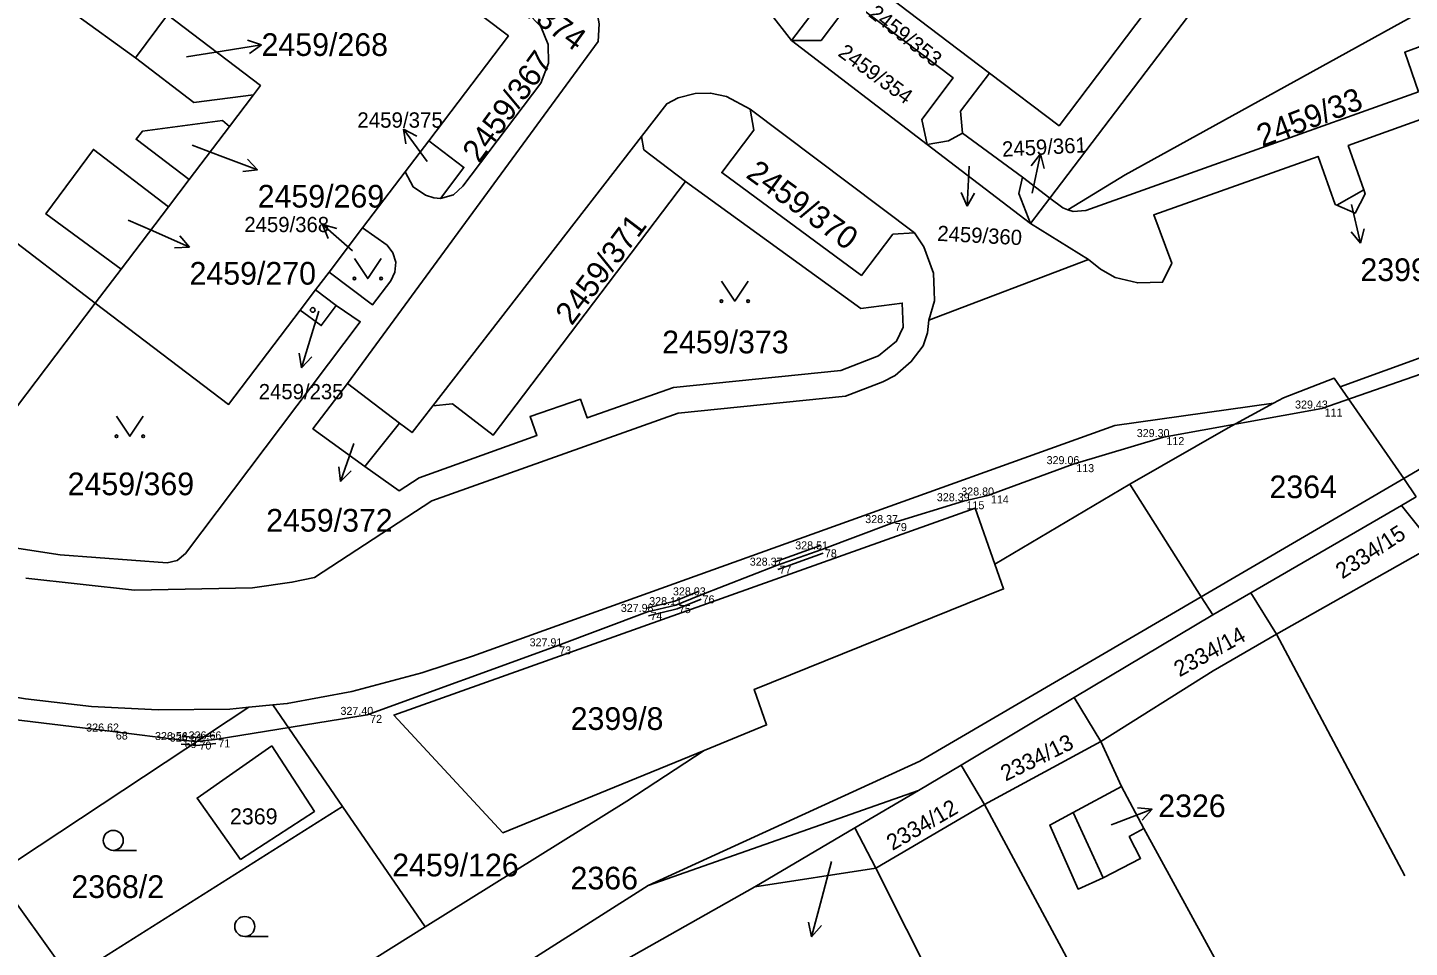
# Model space of a CAD drawing. Extents: x -606208 to -605570, y -1157873 to -1157573.
# Drawn here: x -605860.4 to -605756.7, y -1157769.8 to -1157700.9 of the extents above; entities that cross this region are included whole.
import ezdxf

# ---------------------------------------------------------------- set-up
doc = ezdxf.new("R2010")
doc.units = 0
for name, color, linetype in [('Vrstva 30', 7, 'Continuous'), ('Vrstva 38', 7, 'Continuous'), ('Vrstva 58', 7, 'Continuous'), ('Vrstva 59', 7, 'Continuous'), ('Vrstva 60', 7, 'Continuous'), ('Vrstva 62', 7, 'Continuous'), ('Vrstva 7', 7, 'Continuous')]:
    doc.layers.add(name, color=color, linetype=linetype)

msp = doc.modelspace()

# ---------------------------------------------------------------- linework, layer by layer
at = {"layer": 'Vrstva 30'}
msp.add_lwpolyline([(-605866.2, -1157752.17), (-605853.97, -1157753.65), (-605848.81, -1157754.29), (-605847.7, -1157754.4), (-605846.29, -1157754.24), (-605834.9, -1157752.4), (-605820.72, -1157747.26), (-605813.88, -1157744.68), (-605811.75, -1157744.17), (-605809.97, -1157743.44), (-605804.21, -1157741.21), (-605800.8, -1157739.99), (-605795.55, -1157738.02), (-605790.18, -1157736.38), (-605788.35, -1157735.95), (-605781.95, -1157733.6), (-605775.19, -1157731.57), (-605763.32, -1157729.43), (-605754.76, -1157726.45)], dxfattribs=at)
at = {"layer": 'Vrstva 38'}
for p, q in [((-605804.31, -1157740.93), (-605800.9, -1157739.71)), ((-605804.11, -1157741.49), (-605800.7, -1157740.27))]:
    msp.add_line(p, q, dxfattribs=at)
for points in [[(-605813.95, -1157744.39), (-605811.84, -1157743.88), (-605810.08, -1157743.16)], [(-605813.81, -1157744.97), (-605811.66, -1157744.46), (-605809.86, -1157743.72)]]:
    msp.add_lwpolyline(points, dxfattribs=at)
at = {"layer": 'Vrstva 60'}
for p, q in [((-605763.32, -1157729.43), (-605763.32, -1157729.43)), ((-605775.19, -1157731.57), (-605775.19, -1157731.57)), ((-605781.95, -1157733.6), (-605781.95, -1157733.6)), ((-605788.35, -1157735.95), (-605788.35, -1157735.95)), ((-605790.18, -1157736.38), (-605790.18, -1157736.38)), ((-605795.55, -1157738.02), (-605795.55, -1157738.02)), ((-605800.8, -1157739.99), (-605800.8, -1157739.99)), ((-605804.21, -1157741.21), (-605804.21, -1157741.21)), ((-605811.75, -1157744.17), (-605811.75, -1157744.17)), ((-605809.97, -1157743.44), (-605809.97, -1157743.44)), ((-605813.88, -1157744.68), (-605813.88, -1157744.68)), ((-605820.72, -1157747.26), (-605820.72, -1157747.26)), ((-605834.9, -1157752.4), (-605834.9, -1157752.4)), ((-605853.97, -1157753.65), (-605853.97, -1157753.65)), ((-605848.81, -1157754.29), (-605848.81, -1157754.29)), ((-605847.7, -1157754.4), (-605847.7, -1157754.4)), ((-605846.29, -1157754.24), (-605846.29, -1157754.24))]:
    msp.add_line(p, q, dxfattribs=at)
at = {"layer": 'Vrstva 62'}
for p, q in [((-605798.82, -1157696.23), (-605803.08, -1157701.83)), ((-605788.23, -1157704.27), (-605797.62, -1157697.15)), ((-605852.27, -1157703.13), (-605849.88, -1157699.91)), ((-605842.82, -1157702.15), (-605843.88, -1157701.81)), ((-605803.08, -1157701.83), (-605792.9, -1157709.62)), ((-605848.45, -1157703.06), (-605845.78, -1157702.62)), ((-605845.78, -1157702.62), (-605842.82, -1157702.15)), ((-605842.82, -1157702.15), (-605843.73, -1157702.8)), ((-605845.22, -1157708.27), (-605843.43, -1157705.91)), ((-605793.85, -1157716.25), (-605806.17, -1157706.99)), ((-605845.22, -1157708.27), (-605848.25, -1157712.26)), ((-605830.41, -1157710.91), (-605832.17, -1157708.48)), ((-605832.17, -1157708.48), (-605831.18, -1157709)), ((-605832.17, -1157708.48), (-605831.99, -1157709.59)), ((-605814.33, -1157709.03), (-605829.98, -1157729.23)), ((-605790.26, -1157708.79), (-605785.75, -1157712.09)), ((-605848.02, -1157709.68), (-605845.92, -1157710.47)), ((-605832.06, -1157711.69), (-605830.28, -1157709.35)), ((-605792.9, -1157709.62), (-605785.15, -1157715.55)), ((-605845.92, -1157710.47), (-605843.12, -1157711.54)), ((-605843.12, -1157711.54), (-605843.87, -1157710.72)), ((-605784.42, -1157710.34), (-605785.11, -1157711.22)), ((-605785.04, -1157713.28), (-605784.42, -1157710.34)), ((-605784.42, -1157710.34), (-605784.13, -1157711.43)), ((-605843.12, -1157711.54), (-605844.23, -1157711.65)), ((-605835.24, -1157715.88), (-605832.06, -1157711.69)), ((-605789.76, -1157711.26), (-605789.92, -1157714.26)), ((-605785.75, -1157712.09), (-605783.71, -1157713.66)), ((-605849.81, -1157714.31), (-605848.25, -1157712.26)), ((-605789.92, -1157714.26), (-605790.36, -1157713.23)), ((-605760.16, -1157713.04), (-605762.19, -1157714.18)), ((-605789.92, -1157714.26), (-605789.36, -1157713.28)), ((-605785.15, -1157715.55), (-605783.71, -1157713.66)), ((-605761.08, -1157714.12), (-605760.41, -1157717.04)), ((-605863.59, -1157715.18), (-605855.29, -1157721.53)), ((-605849.81, -1157714.31), (-605853.35, -1157718.98)), ((-605852.83, -1157715.3), (-605850.97, -1157716.11)), ((-605850.97, -1157716.11), (-605848.23, -1157717.33)), ((-605835.99, -1157717.61), (-605838.26, -1157715.64)), ((-605838.26, -1157715.64), (-605837.17, -1157715.92)), ((-605838.26, -1157715.64), (-605837.83, -1157716.68)), ((-605837.76, -1157719.2), (-605835.24, -1157715.88)), ((-605780.82, -1157718.25), (-605785.15, -1157715.55)), ((-605760.41, -1157717.04), (-605761.12, -1157716.18)), ((-605760.41, -1157717.04), (-605760.14, -1157715.96)), ((-605848.23, -1157717.33), (-605849.35, -1157717.38)), ((-605848.23, -1157717.33), (-605848.94, -1157716.47)), ((-605780.82, -1157718.25), (-605792.79, -1157722.8)), ((-605855.29, -1157721.53), (-605853.35, -1157718.98)), ((-605838.78, -1157720.54), (-605837.76, -1157719.2)), ((-605866.35, -1157736.11), (-605855.29, -1157721.53)), ((-605838.78, -1157720.54), (-605839.92, -1157722.05)), ((-605837.22, -1157721.71), (-605838.78, -1157720.54)), ((-605838.52, -1157722.14), (-605838.94, -1157723.5)), ((-605838.94, -1157723.5), (-605839.82, -1157726.37)), ((-605839.82, -1157726.37), (-605840, -1157725.27)), ((-605839.82, -1157726.37), (-605839.05, -1157725.56)), ((-605832.47, -1157730.52), (-605836.37, -1157727.55)), ((-605832.47, -1157730.52), (-605835.08, -1157733.77)), ((-605835.91, -1157732.06), (-605836.89, -1157734.9)), ((-605836.89, -1157734.9), (-605837.03, -1157733.79)), ((-605757.17, -1157734.67), (-605755.85, -1157733.9)), ((-605836.89, -1157734.9), (-605836.09, -1157734.11)), ((-605772.35, -1157743.54), (-605757.17, -1157734.67)), ((-605777.71, -1157735.11), (-605787.84, -1157741.09)), ((-605757.35, -1157736.71), (-605768.64, -1157743.25)), ((-605756.23, -1157736.06), (-605757.35, -1157736.71)), ((-605754.95, -1157739.7), (-605757.35, -1157736.71)), ((-605766.71, -1157746.36), (-605754.95, -1157739.7)), ((-605768.64, -1157743.25), (-605771.49, -1157744.9)), ((-605766.71, -1157746.36), (-605768.64, -1157743.25)), ((-605793.46, -1157755.86), (-605772.35, -1157743.54)), ((-605771.49, -1157744.9), (-605781.88, -1157751.1)), ((-605781.88, -1157751.1), (-605790.36, -1157756.16)), ((-605779.89, -1157754.4), (-605781.88, -1157751.1)), ((-605862.77, -1157764.37), (-605843.78, -1157751.83)), ((-605843.78, -1157751.83), (-605841.98, -1157751.66)), ((-605841.98, -1157751.66), (-605836.75, -1157759.27)), ((-605788.6, -1157759.11), (-605779.89, -1157754.4)), ((-605779.89, -1157754.4), (-605778.33, -1157757.77)), ((-605813.83, -1157765.2), (-605793.46, -1157755.86)), ((-605790.36, -1157756.16), (-605793.55, -1157758.06)), ((-605788.6, -1157759.11), (-605790.36, -1157756.16)), ((-605778.33, -1157757.77), (-605776.65, -1157760.91)), ((-605798.33, -1157760.88), (-605793.55, -1157758.06)), ((-605830.55, -1157768.29), (-605836.75, -1157759.27)), ((-605796.76, -1157763.9), (-605788.6, -1157759.11)), ((-605781.97, -1157759.71), (-605779.7, -1157764.62)), ((-605778.83, -1157760.55), (-605776.03, -1157759.48)), ((-605776.03, -1157759.48), (-605777.14, -1157759.37)), ((-605776.03, -1157759.48), (-605776.78, -1157760.3)), ((-605805.82, -1157765.3), (-605798.33, -1157760.88)), ((-605796.76, -1157763.9), (-605798.33, -1157760.88)), ((-605779.1, -1157760.65), (-605778.83, -1157760.55)), ((-605853.94, -1157762.56), (-605852.19, -1157762.56)), ((-605805.82, -1157765.3), (-605796.76, -1157763.9)), ((-605800.08, -1157763.39), (-605800.81, -1157766.14)), ((-605821.47, -1157774.11), (-605805.82, -1157765.3)), ((-605800.81, -1157766.14), (-605801.59, -1157769.04)), ((-605801.59, -1157769.04), (-605801.81, -1157767.94)), ((-605830.55, -1157768.29), (-605850.18, -1157780.56)), ((-605844.08, -1157769.02), (-605842.33, -1157769.02)), ((-605801.59, -1157769.04), (-605800.84, -1157768.2))]:
    msp.add_line(p, q, dxfattribs=at)
for points in [[(-605787.77, -1157681.67), (-605783.63, -1157676.22), (-605765.7, -1157689.93), (-605783.71, -1157713.66)], [(-605716.01, -1157685.76), (-605715.64, -1157687.2), (-605715.58, -1157688.54), (-605716.2, -1157690.79), (-605716.23, -1157690.9), (-605717.74, -1157692.92), (-605719.64, -1157695.24), (-605723.87, -1157699.35), (-605728.04, -1157702.31), (-605731.16, -1157703.8), (-605733.45, -1157704.9), (-605734.89, -1157705.42), (-605744.73, -1157708.97), (-605746.18, -1157708.32), (-605747.24, -1157705.75), (-605747.64, -1157704.79), (-605761.33, -1157709.71), (-605760.16, -1157713.04)], [(-605803.08, -1157701.83), (-605804.76, -1157699.67), (-605805.66, -1157696.95), (-605805.49, -1157694.72), (-605804.82, -1157692.87)], [(-605744.75, -1157693.52), (-605778.05, -1157711.9), (-605782.37, -1157714.52)], [(-605836.37, -1157727.55), (-605817.59, -1157701.91), (-605817.5, -1157700.57), (-605817.68, -1157699.61), (-605819.13, -1157697.22), (-605820.74, -1157695.98), (-605822.96, -1157694.27)], [(-605831.89, -1157695.74), (-605830.54, -1157693.93), (-605822.95, -1157699.67), (-605821.88, -1157700.77), (-605821.33, -1157702.13), (-605821.3, -1157703.54), (-605821.87, -1157705.02), (-605827.73, -1157712.76), (-605828.43, -1157713.4), (-605829.39, -1157713.68)], [(-605852.27, -1157703.13), (-605857.04, -1157699.67), (-605854.61, -1157696.32)], [(-605830.28, -1157709.35), (-605824.31, -1157701.49), (-605831.89, -1157695.74)], [(-605774.39, -1157696.8), (-605783.02, -1157708.22), (-605788.23, -1157704.27)], [(-605803.08, -1157701.83), (-605800.86, -1157701.84), (-605798.6, -1157698.86), (-605790.97, -1157704.62), (-605793.31, -1157707.75), (-605792.9, -1157709.62)], [(-605849.88, -1157699.91), (-605842.9, -1157705.21), (-605843.43, -1157705.91)], [(-605756.06, -1157705.69), (-605757.1, -1157702.71), (-605752.53, -1157701.03), (-605752.17, -1157702.07)], [(-605843.43, -1157705.91), (-605847.89, -1157706.47), (-605852.27, -1157703.13)], [(-605788.23, -1157704.27), (-605790.41, -1157707.12), (-605790.26, -1157708.79)], [(-605806.17, -1157706.99), (-605807.96, -1157706.03), (-605809.15, -1157705.78), (-605810.3, -1157705.81), (-605811.58, -1157706.12), (-605812.43, -1157706.58), (-605814.33, -1157709.03)], [(-605782.37, -1157714.52), (-605781.95, -1157714.66), (-605781, -1157714.58), (-605756.06, -1157705.69)], [(-605793.85, -1157716.25), (-605795.47, -1157716.35), (-605797.84, -1157719.45), (-605808.31, -1157711.74), (-605805.9, -1157708.56), (-605806.17, -1157706.99)], [(-605848.25, -1157712.26), (-605852.23, -1157709.24), (-605851.76, -1157708.64), (-605845.74, -1157707.82), (-605845.22, -1157708.27)], [(-605761.94, -1157727.8), (-605745.07, -1157721.67), (-605736.69, -1157715.48), (-605737.67, -1157713.93), (-605737.74, -1157713.82), (-605736.68, -1157713.43), (-605729.27, -1157710.74), (-605724.56, -1157708.36), (-605723.31, -1157707.49)], [(-605814.33, -1157709.03), (-605814.16, -1157710.02), (-605811.02, -1157712.41)], [(-605790.26, -1157708.79), (-605791.31, -1157709.35), (-605792.9, -1157709.62)], [(-605853.35, -1157718.98), (-605858.99, -1157714.84), (-605855.43, -1157710), (-605849.81, -1157714.31)], [(-605830.28, -1157709.35), (-605827.65, -1157711.35), (-605829.39, -1157713.68)], [(-605762.19, -1157714.18), (-605762.31, -1157714.12), (-605763.59, -1157710.52), (-605775.92, -1157714.91), (-605774.57, -1157718.52), (-605775.25, -1157719.96), (-605777.12, -1157720.01), (-605778.8, -1157719.6), (-605779.9, -1157718.99), (-605780.82, -1157718.25)], [(-605829.39, -1157713.68), (-605829.9, -1157713.64), (-605830.53, -1157713.42), (-605831.44, -1157712.81), (-605832.06, -1157711.69)], [(-605785.75, -1157712.09), (-605786.03, -1157713.31), (-605785.15, -1157715.55)], [(-605811.02, -1157712.41), (-605797.88, -1157721.92), (-605794.78, -1157721.52), (-605794.72, -1157723.32), (-605795.2, -1157724.38), (-605796.55, -1157725.47), (-605799.38, -1157726.57), (-605811.93, -1157727.84), (-605818.4, -1157730.13), (-605818.91, -1157728.73), (-605822.68, -1157730.03), (-605822.17, -1157731.46), (-605830.99, -1157734.63), (-605832.5, -1157735.6), (-605835.08, -1157733.77)], [(-605829.98, -1157729.23), (-605828.49, -1157729.08), (-605825.46, -1157731.43), (-605811.02, -1157712.41)], [(-605760.16, -1157713.04), (-605760.06, -1157713.33), (-605760.82, -1157714.79), (-605762.19, -1157714.18)], [(-605782.37, -1157714.52), (-605782.73, -1157714.39), (-605783.71, -1157713.66)], [(-605835.24, -1157715.88), (-605833.41, -1157717.18), (-605832.97, -1157717.76), (-605832.76, -1157718.46), (-605832.82, -1157719.2), (-605833.12, -1157719.85), (-605834.5, -1157721.65), (-605837.76, -1157719.2)], [(-605792.79, -1157722.8), (-605792.37, -1157721.35), (-605792.39, -1157720.6), (-605792.43, -1157719.28), (-605793.15, -1157717.31), (-605793.85, -1157716.25)], [(-605835.86, -1157718.18), (-605834.86, -1157719.68), (-605833.86, -1157718.18)], [(-605808.34, -1157719.87), (-605807.34, -1157721.37), (-605806.34, -1157719.87)], [(-605855.29, -1157721.53), (-605845.29, -1157729.12), (-605839.92, -1157722.05)], [(-605837.22, -1157721.71), (-605835.42, -1157722.92), (-605848.53, -1157740.31), (-605849.14, -1157740.82), (-605849.91, -1157741), (-605857.93, -1157740.41), (-605861.35, -1157739.87), (-605866.35, -1157736.11)], [(-605839.92, -1157722.05), (-605838.35, -1157723.21), (-605837.22, -1157721.71)], [(-605792.79, -1157722.8), (-605792.88, -1157723.76), (-605793.22, -1157724.74), (-605794.1, -1157725.91), (-605795.31, -1157726.94), (-605796.22, -1157727.42), (-605799.02, -1157728.49), (-605811.59, -1157729.77), (-605830.05, -1157736.36), (-605838.84, -1157742.09), (-605840.54, -1157742.45), (-605843.49, -1157742.88), (-605852.36, -1157743.04), (-605860.5, -1157742.15)], [(-605835.08, -1157733.77), (-605838.97, -1157730.95), (-605836.37, -1157727.55)], [(-605766.94, -1157729.03), (-605766.18, -1157728.62), (-605762.4, -1157727.14), (-605761.94, -1157727.8)], [(-605761.94, -1157727.8), (-605757.17, -1157734.67), (-605756.23, -1157736.06)], [(-605841.98, -1157751.66), (-605840.89, -1157751.55), (-605836.05, -1157750.65), (-605830.8, -1157749.24), (-605827, -1157747.99), (-605822.28, -1157746.31), (-605778.84, -1157730.7), (-605766.94, -1157729.03)], [(-605829.98, -1157729.23), (-605831.53, -1157731.23), (-605832.47, -1157730.52)], [(-605766.94, -1157729.03), (-605770.34, -1157730.88), (-605777.71, -1157735.11)], [(-605853.69, -1157730.01), (-605852.69, -1157731.51), (-605851.69, -1157730.01)], [(-605771.49, -1157744.9), (-605772.35, -1157743.54), (-605777.71, -1157735.11)], [(-605809.63, -1157755.07), (-605824.72, -1157761.24), (-605832.89, -1157752.42), (-605789.31, -1157736.91), (-605787.84, -1157741.09)], [(-605885.13, -1157739.82), (-605882.17, -1157741.85), (-605883.1, -1157743.55), (-605878.76, -1157746.03), (-605874.17, -1157748.02), (-605869.37, -1157749.5), (-605864.5, -1157750.55), (-605860.51, -1157751.19), (-605855.56, -1157751.77), (-605850.57, -1157752.02), (-605845.2, -1157751.97), (-605843.78, -1157751.83)], [(-605787.84, -1157741.09), (-605787.18, -1157742.95), (-605805.89, -1157750.51), (-605804.95, -1157753.15), (-605809.63, -1157755.07)], [(-605779.89, -1157754.4), (-605771.45, -1157749.09), (-605766.71, -1157746.36)], [(-605766.71, -1157746.36), (-605757.1, -1157764.47)], [(-605842.05, -1157754.73), (-605847.66, -1157758.64), (-605844.41, -1157763.25)], [(-605844.41, -1157763.25), (-605838.86, -1157759.64), (-605842.05, -1157754.73)], [(-605809.63, -1157755.07), (-605815.42, -1157758.86), (-605830.55, -1157768.29)], [(-605776.65, -1157760.91), (-605777.75, -1157761.53), (-605776.91, -1157763.17), (-605779.7, -1157764.62), (-605781.59, -1157765.46), (-605783.72, -1157760.66), (-605781.97, -1157759.71), (-605778.33, -1157757.77)], [(-605793.55, -1157758.06), (-605813.83, -1157765.2), (-605838.4, -1157780.82), (-605841.7, -1157782.15), (-605845.4, -1157782.7), (-605847.36, -1157782.38), (-605850.18, -1157780.56)], [(-605836.75, -1157759.27), (-605857.17, -1157772.16), (-605862.77, -1157764.37)], [(-605788.6, -1157759.11), (-605774.69, -1157785.03), (-605767.41, -1157801.78)], [(-605776.65, -1157760.91), (-605767.41, -1157777.85)], [(-605796.76, -1157763.9), (-605782.91, -1157791.44), (-605771.56, -1157813.31), (-605768.46, -1157822.03)]]:
    msp.add_lwpolyline(points, dxfattribs=at)
for centre, radius in [((-605835.86, -1157719.68), 0.1), ((-605833.86, -1157719.68), 0.1), ((-605808.34, -1157721.37), 0.1), ((-605806.34, -1157721.37), 0.1), ((-605838.98, -1157722.04), 0.175), ((-605853.69, -1157731.51), 0.1), ((-605851.69, -1157731.51), 0.1), ((-605853.94, -1157761.81), 0.75), ((-605844.08, -1157768.27), 0.75)]:
    msp.add_circle(centre, radius, dxfattribs=at)
at = {"layer": 'Vrstva 7'}
for points in [[(-605848.84, -1157754.59), (-605847.7, -1157754.7), (-605846.26, -1157754.54)], [(-605848.78, -1157753.99), (-605847.7, -1157754.1), (-605846.32, -1157753.94)]]:
    msp.add_lwpolyline(points, dxfattribs=at)

# ---------------------------------------------------------------- texts
at = {"layer": 'Vrstva 58'}
for s, p in [('329.43 ', (-605765.32, -1157729.43)), ('329.30 ', (-605777.19, -1157731.57)), ('329.06 ', (-605783.95, -1157733.6)), ('328.39 ', (-605792.18, -1157736.38)), ('328.80 ', (-605790.35, -1157735.95)), ('328.37 ', (-605797.55, -1157738.02)), ('328.51 ', (-605802.8, -1157739.99)), ('328.37 ', (-605806.21, -1157741.21)), ('328.03 ', (-605811.97, -1157743.44)), ('327.98 ', (-605815.88, -1157744.68)), ('328.11 ', (-605813.75, -1157744.17)), ('327.91 ', (-605822.72, -1157747.26)), ('327.40 ', (-605836.9, -1157752.4)), ('326.62 ', (-605855.97, -1157753.65)), ('326.66 ', (-605848.29, -1157754.24)), ('326.56 ', (-605850.81, -1157754.29)), ('326.61 ', (-605849.7, -1157754.4))]:
    msp.add_text(s, height=0.6, dxfattribs=at).set_placement(p)
at = {"layer": 'Vrstva 59'}
for s, p in [(' 111', (-605763.32, -1157730.03)), (' 112', (-605775.19, -1157732.17)), (' 113', (-605781.95, -1157734.2)), (' 114', (-605788.35, -1157736.55)), (' 115', (-605790.18, -1157736.98)), (' 79', (-605795.55, -1157738.62)), (' 78', (-605800.8, -1157740.59)), (' 77', (-605804.21, -1157741.81)), (' 75', (-605811.75, -1157744.77)), (' 76', (-605809.97, -1157744.04)), (' 74', (-605813.88, -1157745.28)), (' 73', (-605820.72, -1157747.86)), (' 72', (-605834.9, -1157753)), (' 68', (-605853.97, -1157754.25)), (' 69', (-605848.81, -1157754.89)), (' 70', (-605847.7, -1157755)), (' 71', (-605846.29, -1157754.84))]:
    msp.add_text(s, height=0.6, dxfattribs=at).set_placement(p)
at = {"layer": 'Vrstva 62'}
for s, height, rotation, p in [('2459/374', 1.7, 324, (-605826.97, -1157697.12)), ('2459/353', 1.139, 322, (-605797.38, -1157699.96)), ('2459/367', 1.7, 54, (-605826.51, -1157711.09)), ('2459/354', 1.139, 324, (-605799.67, -1157702.93)), ('2459/33', 1.7, 21, (-605767.78, -1157709.85)), ('2459/361', 1.139, 3, (-605787.26, -1157710.55)), ('2459/370', 1.7, 324, (-605806.58, -1157712.05)), ('2459/371', 1.7, 53, (-605819.56, -1157723.27)), ('2459/360', 1.139, 357, (-605792.17, -1157716.85)), ('2334/15', 1.2, 33, (-605761.78, -1157742.25)), ('2334/14', 1.2, 29, (-605773.98, -1157749.59)), ('2334/13', 1.2, 26, (-605787.03, -1157757.41)), ('2334/12', 1.2, 30, (-605795.51, -1157762.61))]:
    msp.add_text(s, height=height, rotation=rotation, dxfattribs=at).set_placement(p)
for s, height, p in [('2459/268', 1.7, (-605842.82, -1157702.99)), ('2459/375', 1.15, (-605835.64, -1157708.37)), ('2459/269', 1.7, (-605843.11, -1157714.36)), ('2459/368', 1.139, (-605844.11, -1157716.2)), ('2459/270', 1.7, (-605848.22, -1157720.14)), ('2399/6', 1.7, (-605760.42, -1157719.87)), ('2459/373', 1.7, (-605812.78, -1157725.29)), ('2459/235', 1.139, (-605843.03, -1157728.73)), ('2459/369', 1.7, (-605857.36, -1157735.93)), ('2364', 1.7, (-605767.24, -1157736.15)), ('2459/372', 1.7, (-605842.47, -1157738.66)), ('2399/8', 1.7, (-605819.64, -1157753.53)), ('2326', 1.7, (-605775.58, -1157760.07)), ('2369', 1.2, (-605845.19, -1157760.61)), ('2459/126', 1.7, (-605833.02, -1157764.51)), ('2366', 1.7, (-605819.65, -1157765.49)), ('2368/2', 1.7, (-605857.08, -1157766.13))]:
    msp.add_text(s, height=height, dxfattribs=at).set_placement(p)

doc.saveas('drawing.dxf')
